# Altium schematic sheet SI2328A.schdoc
size 127 x 101 mm
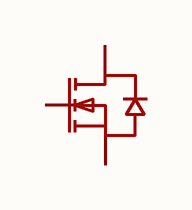
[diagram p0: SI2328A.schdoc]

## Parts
Q?  si2328a  [SOT-23-3_L2.9-W1.3-P1.90-LS2.4-BR]  (value not drawn)

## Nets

Not connected (* = marked no-connect by the designer): Q? 1(G) 2(S) 3(D)

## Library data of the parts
Q? = si2328a: 数量:1个N沟道;漏源电压(Vdss):100V;连续漏极电流(Id):1.5A;导通电阻(RDS(on)):245mΩ@10V；265mΩ@4.5V;耗散功率(Pd):1.25W;阈值电压(Vgs(th)):2V@250uA；4V@250uA;; Manufacturer: UMW(友台半导体); AddInBom: yes; ModelId: c62791f0466c4ae2a892c056b845b0ca; ModelName: SOT-23-3P_L2.9-W1.3-H1.0-LS2.4-P0.95; ModelTransform: 98.425,114.173,0,180,0,0,0.0005,-0.0005,0; Number: 1个N沟道; Drain to Source Voltage: 100V; Current - Continuous Drain(Id): 1.5A; Pd - Power Dissipation: 1.25W; Gate Charge(Qg): 3.3nC@10V; Input Capacitance(Ciss): 1.05nF; Type: N沟道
